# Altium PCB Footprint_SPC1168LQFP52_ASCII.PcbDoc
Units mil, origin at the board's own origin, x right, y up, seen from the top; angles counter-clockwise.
Board outline 6000 x 4000 mil, 2 copper layers (Top Layer, Bottom Layer); 1 components, 0 nets, 52 pads, 0 vias.
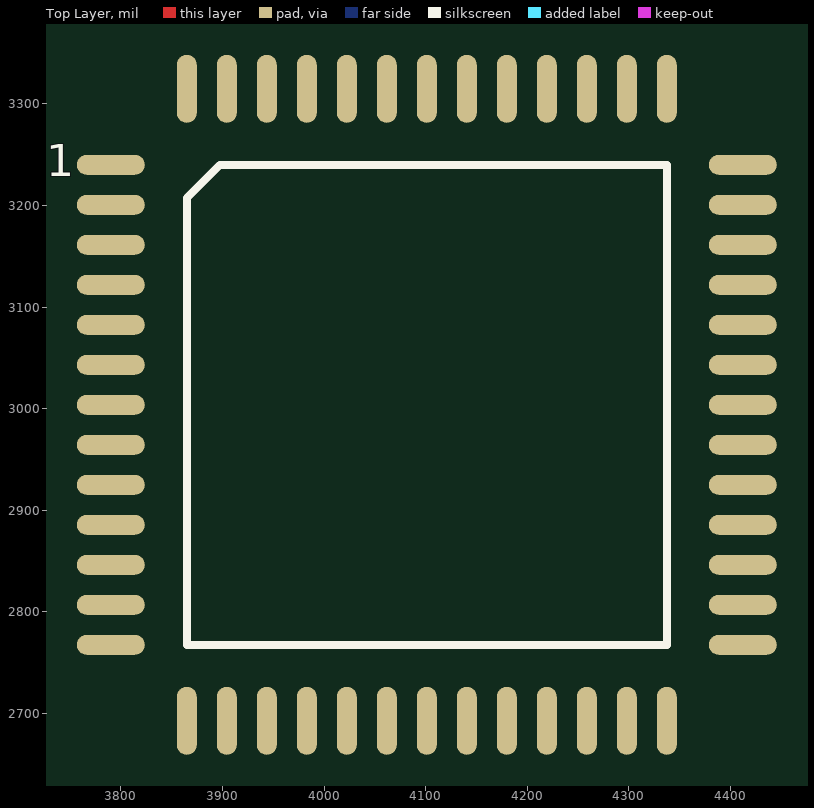
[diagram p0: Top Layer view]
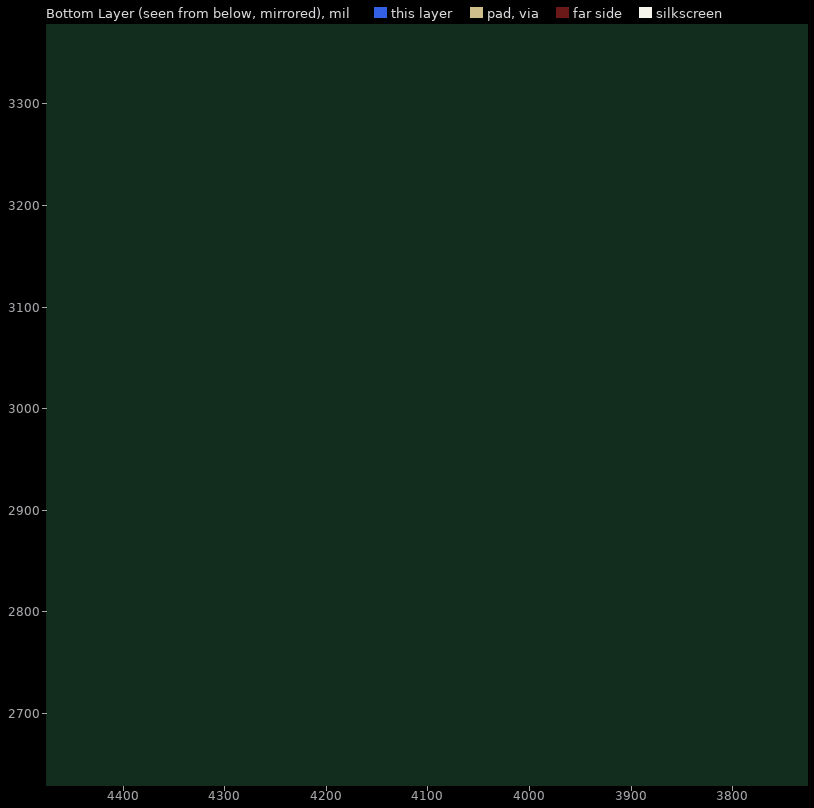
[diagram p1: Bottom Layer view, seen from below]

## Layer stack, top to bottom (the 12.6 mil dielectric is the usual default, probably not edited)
Top Solder: solder mask 0.4, Solder Resist, Dk 3.5
Top Layer: signal copper 1.4
Dielectric 1: dielectric 12.6, FR-4, Dk 4.8
Bottom Layer: signal copper 1.4
Bottom Solder: solder mask 0.4, Solder Resist, Dk 3.5

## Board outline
1000,1000 7000,1000 7000,5000 1000,5000

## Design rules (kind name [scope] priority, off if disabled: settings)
AssemblyTestPointUsage [All] p0: scope1count=1 scope1_0_kind=Board scope1_0_value=Board scope2count=1 scope2_0_kind=Board scope2_0_value=Board commentlength=0
AssemblyTestpoint [All] p0: scope1count=1 scope1_0_kind=Board scope1_0_value=Board scope2count=1 scope2_0_kind=Board scope2_0_value=Board commentlength=0
Clearance [All] p0: scope1count=1 scope1_0_kind=Board scope1_0_value=Board scope2count=1 scope2_0_kind=Board scope2_0_value=Board commentlength=0 gap=10
Clearance [All] p1: gap=10 ignorepadtopadclearanceinfootprint=FALSE except(0: Arc-Hole Track-Hole SMDPad-Hole THPad-Hole Via-Hole Fill-Hole Poly-Hole Region-Hole Text-Hole)
ComponentClearance [All] p0: scope1count=1 scope1_0_kind=Board scope1_0_value=Board scope2count=1 scope2_0_kind=Board scope2_0_value=Board commentlength=0 gap=10 collisioncheckmode=3
DiffPairsRouting [All] p0: scope1count=1 scope1_0_kind=Board scope1_0_value=Board scope2count=1 scope2_0_kind=Board scope2_0_value=Board commentlength=0
FabricationTestPointUsage [All] p0: scope1count=1 scope1_0_kind=Board scope1_0_value=Board scope2count=1 scope2_0_kind=Board scope2_0_value=Board commentlength=0 valid=0 allowmultiple=FALSE
FabricationTestpoint [All] p0: scope1count=1 scope1_0_kind=Board scope1_0_value=Board scope2count=1 scope2_0_kind=Board scope2_0_value=Board commentlength=0 side=3 testpointundercomponent=TRUE minsize=40 maxsize=100 preferedsize=60 minholesize=0 maxholesize=40 preferedholesize=32 testpointgrid=1
FanoutControl Fanout_BGA [All] p0 off: scope1count=1 scope1_0_kind=Board scope1_0_value=Board scope2count=1 scope2_0_kind=Board scope2_0_value=Board commentlength=69 // Protel DXP Scope 1 Expression Was: IsBGA   Fanout_BGA (Default Rule)
FanoutControl Fanout_LCC [All] p0 off: scope1count=1 scope1_0_kind=Board scope1_0_value=Board scope2count=1 scope2_0_kind=Board scope2_0_value=Board commentlength=69 // Protel DXP Scope 1 Expression Was: IsLCC   Fanout_LCC (Default Rule)
FanoutControl Fanout_SOIC [All] p0 off: scope1count=1 scope1_0_kind=Board scope1_0_value=Board scope2count=1 scope2_0_kind=Board scope2_0_value=Board commentlength=71 // Protel DXP Scope 1 Expression Was: IsSOIC   Fanout_SOIC (Default Rule)
FanoutControl Fanout_Small [All] p0 off: scope1count=1 scope1_0_kind=Board scope1_0_value=Board scope2count=1 scope2_0_kind=Board scope2_0_value=Board commentlength=84 // Protel DXP Scope 1 Expression Was: (CompPinCount < 5)   Fanout_Small (Default Rule)
FanoutControl Fanout_Default [All] p0: scope1count=1 scope1_0_kind=Board scope1_0_value=Board scope2count=1 scope2_0_kind=Board scope2_0_value=Board commentlength=30 // Fanout_Default (Default Rule)
Height [All] p0: scope1count=1 scope1_0_kind=Board scope1_0_value=Board scope2count=1 scope2_0_kind=Board scope2_0_value=Board commentlength=0
HoleSize [All] p0: scope1count=1 scope1_0_kind=Board scope1_0_value=Board scope2count=1 scope2_0_kind=Board scope2_0_value=Board commentlength=0 absolutevalues=TRUE maxlimit=100 minlimit=1 maxpercent=80.000 minpercent=20.000
HoleToHoleClearance [All] p0: scope1count=1 scope1_0_kind=Board scope1_0_value=Board scope2count=1 scope2_0_kind=Board scope2_0_value=Board commentlength=0
LayerPairs [All] p0: scope1count=1 scope1_0_kind=Board scope1_0_value=Board scope2count=1 scope2_0_kind=Board scope2_0_value=Board commentlength=0 enforce=TRUE
MinimumSolderMaskSliver [All] p0: scope1count=1 scope1_0_kind=Board scope1_0_value=Board scope2count=1 scope2_0_kind=Board scope2_0_value=Board commentlength=0
NetAntennae [All] p0: scope1count=1 scope1_0_kind=Board scope1_0_value=Board scope2count=1 scope2_0_kind=Board scope2_0_value=Board commentlength=0
PasteMaskExpansion [All] p0: scope1count=1 scope1_0_kind=Board scope1_0_value=Board scope2count=1 scope2_0_kind=Board scope2_0_value=Board commentlength=0 expansion=0
PlaneClearance [All] p0: scope1count=1 scope1_0_kind=Board scope1_0_value=Board scope2count=1 scope2_0_kind=Board scope2_0_value=Board commentlength=0 clearance=20
PlaneConnect [All] p0: scope1count=1 scope1_0_kind=Board scope1_0_value=Board scope2count=1 scope2_0_kind=Board scope2_0_value=Board commentlength=0 planeconnectstyle=Relief reliefexpansion=20 reliefentries=4 reliefconductorwidth=10 reliefairgap=10
PolygonConnect [All] p0: scope1count=1 scope1_0_kind=Board scope1_0_value=Board scope2count=1 scope2_0_kind=Board scope2_0_value=Board commentlength=0 connectstyle=Relief reliefconductorwidth=10 reliefentries=4 polygonreliefangle="90 Angle"
PolygonConnect [All] p1: connectstyle=Relief reliefconductorwidth=10 reliefentries=4 polygonreliefangle="90 Angle" airgapwidth=10
RoutingCorners [All] p0: scope1count=1 scope1_0_kind=Board scope1_0_value=Board scope2count=1 scope2_0_kind=Board scope2_0_value=Board commentlength=0 cornerstyle=45-Degree minsetback=100 maxsetback=100
RoutingLayers [All] p0: scope1count=1 scope1_0_kind=Board scope1_0_value=Board scope2count=1 scope2_0_kind=Board scope2_0_value=Board commentlength=0 top layer=Automatic bottom layer=Automatic
RoutingPriority [All] p0: scope1count=1 scope1_0_kind=Board scope1_0_value=Board scope2count=1 scope2_0_kind=Board scope2_0_value=Board commentlength=0
RoutingTopology [All] p0: scope1count=1 scope1_0_kind=Board scope1_0_value=Board scope2count=1 scope2_0_kind=Board scope2_0_value=Board commentlength=0 topology=Shortest
RoutingVias [All] p0: scope1count=1 scope1_0_kind=Board scope1_0_value=Board scope2count=1 scope2_0_kind=Board scope2_0_value=Board commentlength=0 holewidth=28 width=50 viastyle="Through Hole" minholewidth=28 minwidth=50 maxholewidth=28 maxwidth=50
RoutingVias [All] p1: holewidth=28 width=50 viastyle="Through Hole" minholewidth=28 minwidth=50 maxholewidth=28 maxwidth=50
ShortCircuit [All] p0: scope1count=1 scope1_0_kind=Board scope1_0_value=Board scope2count=1 scope2_0_kind=Board scope2_0_value=Board commentlength=0 allowed=FALSE
SilkToBoardRegionClearance [All] p0: scope1count=1 scope1_0_kind=Board scope1_0_value=Board scope2count=1 scope2_0_kind=Board scope2_0_value=Board commentlength=0
SilkToSilkClearance [All] p0: scope1count=1 scope1_0_kind=Board scope1_0_value=Board scope2count=1 scope2_0_kind=Board scope2_0_value=Board commentlength=0
SilkToSolderMaskClearance [All] p0 off: scope1count=1 scope1_0_kind=Board scope1_0_value=Board scope2count=1 scope2_0_kind=Board scope2_0_value=Board commentlength=44 // Protel DXP Scope 1 Expression Was: IsPad
SolderMaskExpansion [All] p0: scope1count=1 scope1_0_kind=Board scope1_0_value=Board scope2count=1 scope2_0_kind=Board scope2_0_value=Board commentlength=0 expansion=4
SolderMaskExpansion [All] p1: expansion=4 istentingtop=FALSE
UnRoutedNet [All] p0: scope1count=1 scope1_0_kind=Board scope1_0_value=Board scope2count=1 scope2_0_kind=Board scope2_0_value=Board commentlength=0
UnpouredPolygon [All] p0: scope1count=1 scope1_0_kind=Board scope1_0_value=Board scope2count=1 scope2_0_kind=Board scope2_0_value=Board commentlength=0
Width [All] p0: scope1count=1 scope1_0_kind=Board scope1_0_value=Board scope2count=1 scope2_0_kind=Board scope2_0_value=Board commentlength=0 maxlimit=10 minlimit=10 preferedwidth=10
Width [All] p1: maxlimit=10 minlimit=10 preferedwidth=10
30 further rules are at their usual default settings.

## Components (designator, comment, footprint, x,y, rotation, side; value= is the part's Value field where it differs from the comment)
? "" LQFP-52-1.0 3790,3240 r0 top

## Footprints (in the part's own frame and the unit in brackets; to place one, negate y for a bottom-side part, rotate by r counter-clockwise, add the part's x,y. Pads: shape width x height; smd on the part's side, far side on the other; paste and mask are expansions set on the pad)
LQFP-52-1.0 [mm] "P-0.5,14*14mm"
  oval 1.7x0.5 smd: 1(0,0) 2(0,-1) 3(0,-2) 4(0,-3) 5(0,-4) 6(0,-5) 7(0,-6) 8(0,-7) 9(0,-8) 10(0,-9) 11(0,-10) 12(0,-11) 13(0,-12) 27(15.8,-12) 28(15.8,-11) 29(15.8,-10) 30(15.8,-9) 31(15.8,-8) 32(15.8,-7) 33(15.8,-6) 34(15.8,-5) 35(15.8,-4) 36(15.8,-3) 37(15.8,-2) 38(15.8,-1) 39(15.8,0)
  oval 0.5x1.7 smd: 14(1.9,-13.9) 15(2.9,-13.9) 16(3.9,-13.9) 17(4.9,-13.9) 18(5.9,-13.9) 19(6.9,-13.9) 20(7.9,-13.9) 21(8.9,-13.9) 22(9.9,-13.9) 23(10.9,-13.9) 24(11.9,-13.9) 25(12.9,-13.9) 26(13.9,-13.9) 40(13.9,1.9) 41(12.9,1.9) 42(11.9,1.9) 43(10.9,1.9) 44(9.9,1.9) 45(8.9,1.9) 46(7.9,1.9) 47(6.9,1.9) 48(5.9,1.9) 49(4.9,1.9) 50(3.9,1.9) 51(2.9,1.9) 52(1.9,1.9)
  silkscreen extent 1.9,-12 13.9,0

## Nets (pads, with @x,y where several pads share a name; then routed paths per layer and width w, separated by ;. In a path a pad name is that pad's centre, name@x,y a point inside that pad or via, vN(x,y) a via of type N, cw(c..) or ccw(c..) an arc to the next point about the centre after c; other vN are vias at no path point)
pads on no net: ?.1 ?.2 ?.3 ?.4 ?.5 ?.6 ?.7 ?.8 ?.9 ?.10 ?.11 ?.12 ?.13 ?.14 ?.15 ?.16 ?.17 ?.18 ?.19 ?.20 ?.21 ?.22 ?.23 ?.24 ?.25 ?.26 ?.27 ?.28 ?.29 ?.30 ?.31 ?.32 ?.33 ?.34 ?.35 ?.36 ?.37 ?.38 ?.39 ?.40 ?.41 ?.42 ?.43 ?.44 ?.45 ?.46 ?.47 ?.48 ?.49 ?.50 ?.51 ?.52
